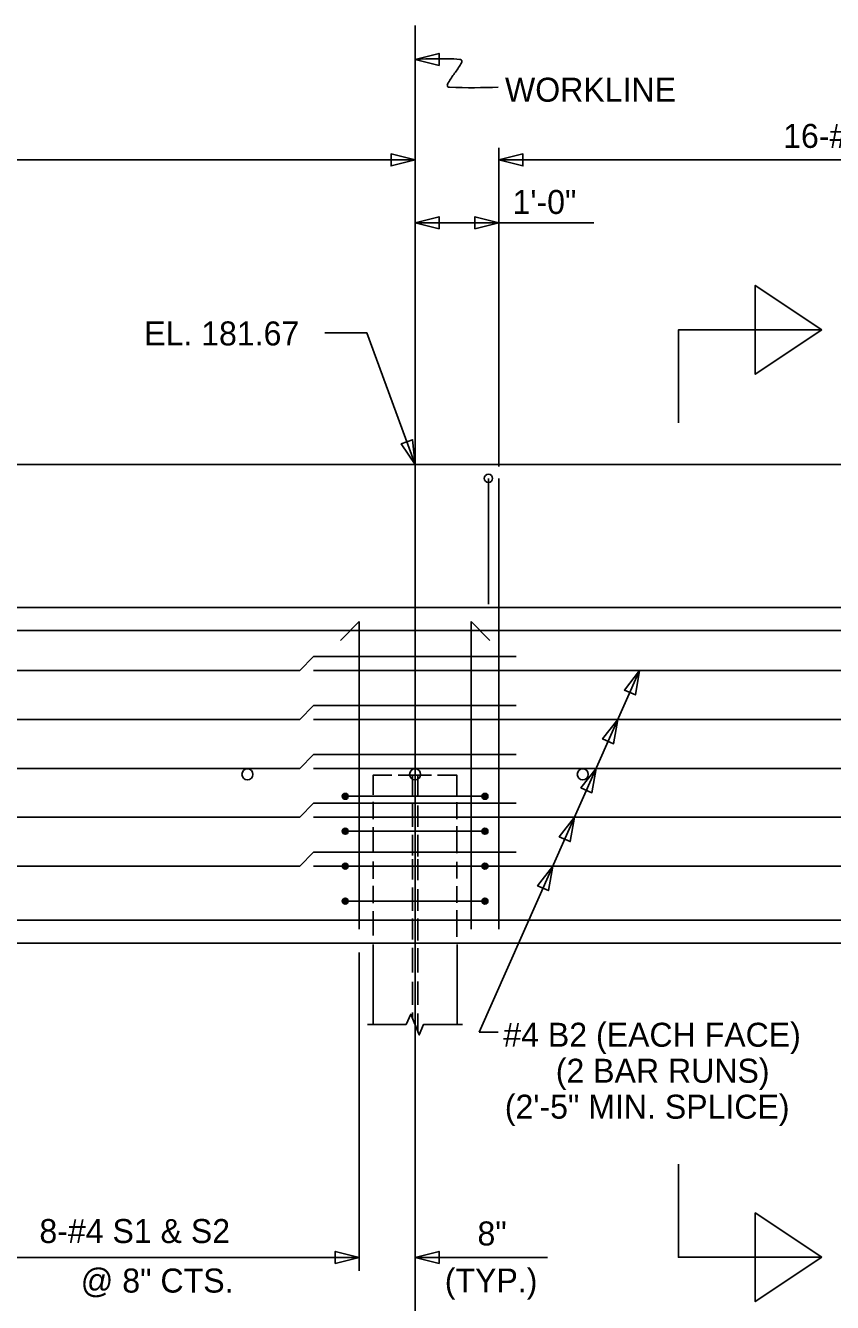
# Model space of a CAD drawing. Extents: x -41 to 251, y -169 to 237.
# Drawn here: x 114.12 to 123.74, y -40.94 to -25.71 of the extents above; entities that cross this region are included whole.
import ezdxf

# ---------------------------------------------------------------- set-up
doc = ezdxf.new("R2010")
doc.units = 0
for name, color, linetype in [('Arrowhead Terminators CELL', 7, 'Continuous'), ('Dimension Lines', 7, 'Continuous'), ('Mis -L- Lines', 7, 'Continuous'), ('Mis Object Lines', 7, 'Continuous'), ('Rebar Lines', 7, 'Continuous'), ('Rebar Lines CELL', 7, 'Continuous'), ('Sub End Bent Cap Lines CELL', 7, 'Continuous'), ('Text', 7, 'Continuous')]:
    doc.layers.add(name, color=color, linetype=linetype)

# ---------------------------------------------------------------- blocks, each defined once
blk = doc.blocks.new('AH')
at = {"layer": 'Sub End Bent Cap Lines CELL'}
blk.add_lwpolyline([(0, 0), (-1.25, 0.312), (-1.25, -0.312)], close=True, dxfattribs=at)

msp = doc.modelspace()

# ---------------------------------------------------------------- linework, layer by layer
at = {"layer": 'Arrowhead Terminators CELL'}
for points in [[(118.763, -26.113), (119.049, -26.185), (119.049, -26.042)], [(118.763, -27.312), (118.477, -27.241), (118.477, -27.384)], [(119.763, -27.312), (120.049, -27.384), (120.049, -27.241)], [(118.763, -28.062), (119.049, -28.134), (119.049, -27.991)], [(123.615, -29.339), (122.821, -29.868), (122.821, -28.81)], [(118.763, -30.944), (118.732, -30.65), (118.597, -30.7)], [(121.44, -33.402), (121.259, -33.635), (121.39, -33.693)], [(121.181, -33.986), (121, -34.218), (121.131, -34.276)], [(120.922, -34.569), (120.741, -34.801), (120.872, -34.86)], [(120.663, -35.152), (120.482, -35.385), (120.613, -35.443)], [(120.404, -35.735), (120.223, -35.968), (120.354, -36.026)], [(123.615, -40.4), (122.821, -39.871), (122.821, -40.929)], [(118.096, -40.402), (117.81, -40.474), (117.81, -40.331)], [(118.763, -40.402), (119.049, -40.331), (119.049, -40.474)]]:
    msp.add_lwpolyline(points, close=True, dxfattribs=at)
at = {"layer": 'Dimension Lines'}
for p, q in [((119.763, -30.967), (119.763, -27.169)), ((102.846, -27.312), (118.763, -27.312)), ((119.763, -27.312), (134.763, -27.312)), ((118.763, -28.062), (120.895, -28.062)), ((121.44, -33.402), (119.526, -37.714)), ((118.096, -36.767), (118.096, -40.562)), ((119.526, -37.714), (119.755, -37.714)), ((118.096, -40.402), (113.43, -40.402)), ((120.341, -40.402), (118.763, -40.402))]:
    msp.add_line(p, q, dxfattribs=at)
for points in [[(118.763, -30.944), (118.186, -29.373), (117.686, -29.373)], [(123.615, -29.339), (121.903, -29.339), (121.903, -30.45)], [(123.615, -40.4), (121.903, -40.4), (121.903, -39.289)]]:
    msp.add_lwpolyline(points, dxfattribs=at)
msp.add_spline([(118.763, -26.113), (119.296, -26.113), (119.312, -26.117), (119.319, -26.127), (119.31, -26.165), (119.234, -26.279), (119.158, -26.393), (119.148, -26.43), (119.155, -26.441), (119.172, -26.445), (119.755, -26.446)], degree=3, dxfattribs=at)
at = {"layer": 'Mis -L- Lines'}
for p, q in [((118.763, -25.71), (118.763, -30.944)), ((118.763, -30.944), (118.763, -43.001))]:
    msp.add_line(p, q, dxfattribs=at)
at = {"layer": 'Mis Object Lines'}
for p, q in [((102.555, -30.944), (125.46, -30.944)), ((99.263, -32.652), (138.263, -32.652)), ((102.851, -36.652), (132.579, -36.652))]:
    msp.add_line(p, q, dxfattribs=at)
at = {"layer": 'Rebar Lines'}
for p, q in [((119.638, -32.61), (119.638, -31.11)), ((119.763, -36.485), (119.763, -31.11)), ((118.096, -32.819), (117.872, -33.043)), ((118.096, -36.485), (118.096, -32.819)), ((119.43, -32.819), (119.654, -33.043)), ((119.43, -36.485), (119.43, -32.819)), ((99.97, -32.923), (137.551, -32.923)), ((117.387, -33.402), (117.55, -33.236)), ((117.55, -33.236), (119.967, -33.236)), ((99.512, -33.402), (117.387, -33.402)), ((117.55, -33.402), (138.009, -33.402)), ((117.387, -33.986), (117.55, -33.819)), ((117.55, -33.819), (119.967, -33.819)), ((99.512, -33.986), (117.387, -33.986)), ((117.55, -33.986), (138.009, -33.986)), ((117.387, -34.569), (117.55, -34.402)), ((117.55, -34.402), (119.967, -34.402)), ((99.512, -34.569), (117.387, -34.569)), ((117.55, -34.569), (138.009, -34.569)), ((118.763, -34.501), (118.763, -36.257)), ((118.732, -34.895), (118.732, -34.652)), ((118.795, -34.901), (118.795, -34.652)), ((117.387, -35.152), (117.55, -34.986)), ((117.55, -34.986), (119.967, -34.986)), ((118.732, -35.267), (118.732, -34.988)), ((118.795, -35.267), (118.795, -35.011)), ((99.512, -35.152), (117.387, -35.152)), ((117.55, -35.152), (138.009, -35.152)), ((118.732, -35.609), (118.732, -35.36)), ((118.795, -35.621), (118.795, -35.36)), ((117.387, -35.735), (117.55, -35.569)), ((117.55, -35.569), (119.967, -35.569)), ((99.512, -35.735), (117.387, -35.735)), ((117.55, -35.735), (138.009, -35.735)), ((118.732, -35.895), (118.732, -35.652)), ((118.795, -35.901), (118.795, -35.652)), ((118.732, -36.267), (118.732, -35.988)), ((118.795, -36.267), (118.795, -36.011)), ((99.97, -36.381), (137.551, -36.381)), ((118.732, -36.609), (118.732, -36.36)), ((118.763, -36.362), (118.763, -36.652)), ((118.795, -36.621), (118.795, -36.36)), ((118.262, -36.669), (118.262, -37.621)), ((119.264, -36.669), (119.264, -37.621)), ((118.732, -37.004), (118.732, -36.708)), ((118.763, -36.722), (118.763, -37.928)), ((118.795, -37.004), (118.795, -36.714)), ((118.732, -37.388), (118.732, -37.115)), ((118.795, -37.388), (118.795, -37.109)), ((118.732, -37.556), (118.732, -37.481)), ((118.795, -37.705), (118.795, -37.492))]:
    msp.add_line(p, q, dxfattribs=at)
for points in [[(118.262, -34.886), (118.262, -34.652), (118.485, -34.652)], [(118.561, -34.652), (118.96, -34.652)], [(119.03, -34.652), (119.262, -34.652), (119.262, -34.899)], [(118.262, -35.176), (118.262, -34.968)], [(119.262, -34.974), (119.262, -35.173)], [(118.262, -35.564), (118.262, -35.272)], [(119.262, -35.259), (119.262, -35.58)], [(118.262, -35.886), (118.262, -35.678)], [(119.262, -35.684), (119.262, -35.883)], [(118.262, -36.176), (118.262, -35.968)], [(119.262, -35.974), (119.262, -36.173)], [(118.262, -36.564), (118.262, -36.272)], [(119.262, -36.259), (119.262, -36.58)], [(118.193, -37.622), (118.655, -37.622), (118.71, -37.502), (118.812, -37.747), (118.863, -37.622), (119.33, -37.622)]]:
    msp.add_lwpolyline(points, dxfattribs=at)
for centre, radius in [((119.638, -31.11), 0.0495), ((116.763, -34.641), 0.066), ((118.763, -34.641), 0.066), ((120.763, -34.641), 0.066)]:
    msp.add_circle(centre, radius, dxfattribs=at)
at = {"layer": 'Rebar Lines CELL'}
for p, q in [((119.596, -34.902), (117.93, -34.902)), ((119.596, -35.319), (117.93, -35.319)), ((119.596, -35.735), (117.93, -35.735)), ((119.596, -36.152), (117.93, -36.152))]:
    msp.add_line(p, q, dxfattribs=at)
for points in [[(117.93, -34.867), (117.916, -34.87), (117.905, -34.877), (117.897, -34.889), (117.894, -34.902), (117.897, -34.916), (117.905, -34.927), (117.916, -34.935), (117.93, -34.937), (117.943, -34.935), (117.955, -34.927), (117.962, -34.916), (117.965, -34.902), (117.962, -34.889), (117.955, -34.877), (117.943, -34.87), (117.93, -34.867), (117.93, -34.902), (117.93, -34.937), (117.916, -34.935), (117.93, -34.902), (117.905, -34.927), (117.897, -34.916), (117.93, -34.902), (117.894, -34.902), (117.897, -34.889), (117.93, -34.902), (117.905, -34.877), (117.916, -34.87), (117.93, -34.902), (117.943, -34.87), (117.955, -34.877), (117.93, -34.902), (117.962, -34.889), (117.965, -34.902), (117.93, -34.902), (117.962, -34.916), (117.955, -34.927), (117.93, -34.902), (117.943, -34.935)], [(119.596, -34.867), (119.583, -34.87), (119.571, -34.877), (119.564, -34.889), (119.561, -34.902), (119.564, -34.916), (119.571, -34.927), (119.583, -34.935), (119.596, -34.937), (119.61, -34.935), (119.621, -34.927), (119.629, -34.916), (119.632, -34.902), (119.629, -34.889), (119.621, -34.877), (119.61, -34.87), (119.596, -34.867), (119.596, -34.902), (119.596, -34.937), (119.583, -34.935), (119.596, -34.902), (119.571, -34.927), (119.564, -34.916), (119.596, -34.902), (119.561, -34.902), (119.564, -34.889), (119.596, -34.902), (119.571, -34.877), (119.583, -34.87), (119.596, -34.902), (119.61, -34.87), (119.621, -34.877), (119.596, -34.902), (119.629, -34.889), (119.632, -34.902), (119.596, -34.902), (119.629, -34.916), (119.621, -34.927), (119.596, -34.902), (119.61, -34.935)], [(117.93, -35.284), (117.916, -35.286), (117.905, -35.294), (117.897, -35.305), (117.894, -35.319), (117.897, -35.332), (117.905, -35.344), (117.916, -35.351), (117.93, -35.354), (117.943, -35.351), (117.955, -35.344), (117.962, -35.332), (117.965, -35.319), (117.962, -35.305), (117.955, -35.294), (117.943, -35.286), (117.93, -35.284), (117.93, -35.319), (117.93, -35.354), (117.916, -35.351), (117.93, -35.319), (117.905, -35.344), (117.897, -35.332), (117.93, -35.319), (117.894, -35.319), (117.897, -35.305), (117.93, -35.319), (117.905, -35.294), (117.916, -35.286), (117.93, -35.319), (117.943, -35.286), (117.955, -35.294), (117.93, -35.319), (117.962, -35.305), (117.965, -35.319), (117.93, -35.319), (117.962, -35.332), (117.955, -35.344), (117.93, -35.319), (117.943, -35.351)], [(119.596, -35.284), (119.583, -35.286), (119.571, -35.294), (119.564, -35.305), (119.561, -35.319), (119.564, -35.332), (119.571, -35.344), (119.583, -35.351), (119.596, -35.354), (119.61, -35.351), (119.621, -35.344), (119.629, -35.332), (119.632, -35.319), (119.629, -35.305), (119.621, -35.294), (119.61, -35.286), (119.596, -35.284), (119.596, -35.319), (119.596, -35.354), (119.583, -35.351), (119.596, -35.319), (119.571, -35.344), (119.564, -35.332), (119.596, -35.319), (119.561, -35.319), (119.564, -35.305), (119.596, -35.319), (119.571, -35.294), (119.583, -35.286), (119.596, -35.319), (119.61, -35.286), (119.621, -35.294), (119.596, -35.319), (119.629, -35.305), (119.632, -35.319), (119.596, -35.319), (119.629, -35.332), (119.621, -35.344), (119.596, -35.319), (119.61, -35.351)], [(117.93, -35.7), (117.916, -35.703), (117.905, -35.711), (117.897, -35.722), (117.894, -35.735), (117.897, -35.749), (117.905, -35.76), (117.916, -35.768), (117.93, -35.771), (117.943, -35.768), (117.955, -35.76), (117.962, -35.749), (117.965, -35.735), (117.962, -35.722), (117.955, -35.711), (117.943, -35.703), (117.93, -35.7), (117.93, -35.735), (117.93, -35.771), (117.916, -35.768), (117.93, -35.735), (117.905, -35.76), (117.897, -35.749), (117.93, -35.735), (117.894, -35.735), (117.897, -35.722), (117.93, -35.735), (117.905, -35.711), (117.916, -35.703), (117.93, -35.735), (117.943, -35.703), (117.955, -35.711), (117.93, -35.735), (117.962, -35.722), (117.965, -35.735), (117.93, -35.735), (117.962, -35.749), (117.955, -35.76), (117.93, -35.735), (117.943, -35.768)], [(119.596, -35.7), (119.583, -35.703), (119.571, -35.711), (119.564, -35.722), (119.561, -35.735), (119.564, -35.749), (119.571, -35.76), (119.583, -35.768), (119.596, -35.771), (119.61, -35.768), (119.621, -35.76), (119.629, -35.749), (119.632, -35.735), (119.629, -35.722), (119.621, -35.711), (119.61, -35.703), (119.596, -35.7), (119.596, -35.735), (119.596, -35.771), (119.583, -35.768), (119.596, -35.735), (119.571, -35.76), (119.564, -35.749), (119.596, -35.735), (119.561, -35.735), (119.564, -35.722), (119.596, -35.735), (119.571, -35.711), (119.583, -35.703), (119.596, -35.735), (119.61, -35.703), (119.621, -35.711), (119.596, -35.735), (119.629, -35.722), (119.632, -35.735), (119.596, -35.735), (119.629, -35.749), (119.621, -35.76), (119.596, -35.735), (119.61, -35.768)], [(117.93, -36.117), (117.916, -36.12), (117.905, -36.127), (117.897, -36.139), (117.894, -36.152), (117.897, -36.166), (117.905, -36.177), (117.916, -36.185), (117.93, -36.187), (117.943, -36.185), (117.955, -36.177), (117.962, -36.166), (117.965, -36.152), (117.962, -36.139), (117.955, -36.127), (117.943, -36.12), (117.93, -36.117), (117.93, -36.152), (117.93, -36.187), (117.916, -36.185), (117.93, -36.152), (117.905, -36.177), (117.897, -36.166), (117.93, -36.152), (117.894, -36.152), (117.897, -36.139), (117.93, -36.152), (117.905, -36.127), (117.916, -36.12), (117.93, -36.152), (117.943, -36.12), (117.955, -36.127), (117.93, -36.152), (117.962, -36.139), (117.965, -36.152), (117.93, -36.152), (117.962, -36.166), (117.955, -36.177), (117.93, -36.152), (117.943, -36.185)], [(119.596, -36.117), (119.583, -36.12), (119.571, -36.127), (119.564, -36.139), (119.561, -36.152), (119.564, -36.166), (119.571, -36.177), (119.583, -36.185), (119.596, -36.187), (119.61, -36.185), (119.621, -36.177), (119.629, -36.166), (119.632, -36.152), (119.629, -36.139), (119.621, -36.127), (119.61, -36.12), (119.596, -36.117), (119.596, -36.152), (119.596, -36.187), (119.583, -36.185), (119.596, -36.152), (119.571, -36.177), (119.564, -36.166), (119.596, -36.152), (119.561, -36.152), (119.564, -36.139), (119.596, -36.152), (119.571, -36.127), (119.583, -36.12), (119.596, -36.152), (119.61, -36.12), (119.621, -36.127), (119.596, -36.152), (119.629, -36.139), (119.632, -36.152), (119.596, -36.152), (119.629, -36.166), (119.621, -36.177), (119.596, -36.152), (119.61, -36.185)]]:
    msp.add_lwpolyline(points, dxfattribs=at)

# ---------------------------------------------------------------- block references
at = {"layer": 'Arrowhead Terminators CELL', "xscale": 0.2288, "yscale": 0.2288}
msp.add_blockref('AH', (119.763, -28.062), dxfattribs=at)

# ---------------------------------------------------------------- texts
at = {"layer": 'Text'}
for s, height, p in [('WORKLINE', 0.286, (119.835, -26.618)), ('16-#4 V2 @ 1\'-0" CTS. (EA. FACE)', 0.286, (123.153, -27.169)), ('1\'-0"', 0.286, (119.925, -27.957)), ('EL. 181.67', 0.286, (115.531, -29.525)), ('#4 B2 (EACH FACE)', 0.286, (119.815, -37.889)), ('(2 BAR RUNS)', 0.286, (120.441, -38.318)), ('(2\'-5" MIN. SPLICE)', 0.286, (119.833, -38.747)), ('8-#4 S1 & S2', 0.286, (114.281, -40.23)), ('8"', 0.286, (119.507, -40.259)), ('@ 8" CTS.', 0.2865, (114.774, -40.821)), ('(TYP.)', 0.286, (119.117, -40.82))]:
    msp.add_text(s, height=height, dxfattribs=at).set_placement(p)

doc.saveas('drawing.dxf')
